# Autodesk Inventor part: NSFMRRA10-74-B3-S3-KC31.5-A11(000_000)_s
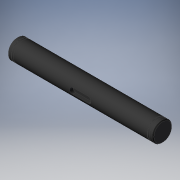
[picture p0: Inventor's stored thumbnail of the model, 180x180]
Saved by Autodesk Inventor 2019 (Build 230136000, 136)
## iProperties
Created: 2022-11
Part Number: NSFMRRA10-74-B3-S3-KC31.5-A11(000_000)_s
Material: Generic
Catalog Web Link: www.cadenas.de
Description: NSFMRR, SFMRR, PSFMRR, SSFMRR, NSFHRR, SFHRR, PSFHRR, SSFHRR, NSFRR, SFRR, PSFRR, SSFRR, NSFMRRA, SFMRRA, PSFMRRA, SSFMRRA, NSFHRRA, SFHRRA, PSFHRRA, SSFHRRA, N
Vendor: MISUMI
Document SubType Name: Modeling
Designer: psAdmin
Manufacturer: MISUMI
Mass: 5.73651 g
Surface Area: 25.2511 cm^2
Volume: 5.73651 cm^3
Density: 1 g/cm^3
Appearance: PSOLRGB-175-175-175
Category: PARTsolutions
Company: MISUMI
Title: NSFMRRA10-74-B3-S3-KC31.5-A11
Author: Cadenas PARTsolutions
Comments: Rotary Shafts - Retaining Ring Grooves on Both Ends - Standard
PSOL_IDENT_0: {$CADENAS_DATA/23d-libs/misumi/metric/11_rotary_shafts/11_components/psfrra/psfrra.prj},808 {VTYP=3D
PSOL_IDENT_1: },{NB=NSFMRRA10-74-B3-S3-KC31.5-A11(000_000)_s},{LINA=NSFMRRA10-74-B3-S3-KC31.5-A11},{NN=NSFMRR, SFM
PSOL_IDENT_2: RR, PSFMRR, SSFMRR, NSFHRR, SFHRR, PSFHRR, SSFHRR, NSFRR, SFRR, PSFRR, SSFRR, NSFMRRA, SFMRRA, PSFMR
PSOL_IDENT_3: RA, SSFMRRA, NSFHRRA, SFHRRA, PSFHRRA, SSFHRRA, NSFRRA, SFRRA, PSFRRA, SSFRRA, HFRRA, PHFRRA, PSFRR
PSOL_IDENT_4: PSFRRA, PSFHRR, PSFHRRA, SSFRR, SSFRRA, SSFHRR, SSFHRRA, PPSFRR, PPSFRRA, PPSFHRR, PPSFHRRA, SSSFRR,
PSOL_IDENT_5: SSSFRRA, SSSFHRR, SSSFHRRA_shaft},{DATE=21.04.2022 07:40:13},{GEOMDATE=27.07.2021 07:13:06},{VERSIO
PSOL_IDENT_6: N=},{LINEID=30},{WBVAR=TS,TYS,MAT,ST,ALT1,L,B,S,ALT2,KC,A,WKC,C,K,E,KZ,Z,ALT3,FC,GALT3,WFC,J,WALT3,V
PSOL_IDENT_7: ,ALT4,SFC,SG,AG,ALT5,UC,ALT7,SC,ALT10,KWC,ALT11,WC,ALT32,CD,ALT34,TCJ,WTCJ,XT,HCJ,WHCJ,XH},{WBNUMERI
PSOL_IDENT_8: C=L,B,S,KC,A,WKC,C,K,E,KZ,Z,FC,GALT3,WFC,J,WALT3,V,SFC,SG,AG,UC,SC,KWC,WC,TCJ,WTCJ,XT,HCJ,WHCJ,XH}
PSOL_IDENT_9: {NB=NSFMRRA10-74-B3-S3-KC31.5-A11(000_000)_s},{LINA=NSFMRRA10-74-B3-S3-KC31.5-A11},{KT=DUMMY},{PN=NS
PSOL_IDENT_10: FMRRA10-74-B3-S3-KC31.5-A11},{TYPE=NSFMRRA},{TS=SWR},{TYS=H9},{TYSALG= 'H9','h9 (Cold-drawn)','H7','
PSOL_IDENT_11: h7 (Ground)','G6','g6 (Ground)' },{MAT=S45C},{MATALG= 'S45C','S45C Equivalent', 'SUS304','SUS304' },
PSOL_IDENT_12: {ST=},{STALG= '','' },{D=10.0},{ALT1=},{ALT1ALG= '','w/o LKC (Changes L Tolerance)','-LKC','with LKC
PSOL_IDENT_13: (Changes L Tolerance)' },{L=74.0},{LALG=[15:800/0.1]},{LMIN=15},{LMAX=800},{NOTE=25},{B=3.0},{BALG=
PSOL_IDENT_14: [3:70/0.1]},{BMAX=70},{S=3.0},{SALG=[3:69/0.1]},{SMAX=69},{MM=1.15},{DD=9.6},{ARR=STWS10},{ALT2=KC},
PSOL_IDENT_15: {ALT2ALG= '', 'w/o Key Grooves','KC','with KC (Key Groove)','WKC','with WKC (Two Key Grooves)','KCWK
PSOL_IDENT_16: C','with KC + WKC (Three Key Grooves)','KZ','with KC + WKC + KZ (Four Key Grooves)' },{ALT2PN=-KC31.
PSOL_IDENT_17: 5-A11},{KC=31.5},{KCALG=[0:71/0.1]},{KCMIN=0},{KCMAX=71},{A=11.0},{AALG=[3:42.5/0.1]},{AMIN=3},{AMAX=
PSOL_IDENT_18: 42.5},{WKC=0.0},{WKCALG=[0]},{WKCMIN=0},{WKCMAX=0},{C=0.0},{CALG=[0]},{CMIN=3},{CMAX=0},{K=0.0},{KAL
PSOL_IDENT_19: G=[0]},{KMIN=0},{KMAX=69},{E=0.0},{EALG=[0]},{EMIN=3},{EMAX=72},{KZ=0.0},{KZALG=[0]},{KZMIN=76},{KZM
PSOL_IDENT_20: AX=71},{Z=0.0},{ZALG=[0]},{ZMIN=3},{ZMAX=74},{CIFKC=2},{CIFWKC=1},{CIFK=1},{CIFKZ=2},{PCUT3D=0},{QCU
PSOL_IDENT_21: T3D=0},{BB=3},{BBALT2=3},{TT=1.8},{TTALT2=1.8},{ALT3=},{ALT3ALG= '', 'w/o Set Screw Flat','FC','with
PSOL_IDENT_22: FC (Adds a Set Screw Flat)','WFC','with WFC (Adds Two Set Screw Flats)','FCWFC','with FC + WFC (Add
PSOL_IDENT_23: s Three Set Screw Flats)' },{ALT3PN=},{FC=0},{FCALG=[0]},{FCMIN=0},{FCMAX=73},{GALT3=0},{GALT3ALG=[0
PSOL_IDENT_24: ]},{GALT3MIN=1},{GALT3MAX=70},{GALT3MAX2=68},{GALT3MAX3=70},{WFC=0},{WFCALG=[0]},{WFCMIN=0},{WFCMIN2=
PSOL_IDENT_25: 2},{WFCMAX=70},{WFCMAX2=-3},{WFCMAX3=-4},{J=0},{JALG=[0]},{JMIN=1},{JMAX=70},{JMAX2=-2},{JMAX3=-5},{
PSOL_IDENT_26: WALT3=0},{WALT3ALG=[0]},{WALT3MIN=0},{WALT3MIN2=76},{WALT3MAX=71},{WALT3MAX2=71},{V=0},{VALG=[0]},{V
PSOL_IDENT_27: MIN=1},{VMAX=70},{VMAX2=70},{CIFFC=0},{H=0},{ALT4=},{ALT4ALG= '', 'w/o SFC (2 Set Screw Flats (Angle
PSOL_IDENT_28: Specified))', 'SFC'  , 'with SFC (2 Set Screw Flats (Angle Specified))'},{ALT4PN=},{SFC=0},{SFCALG=
PSOL_IDENT_29: [0]},{SFCMIN=0},{SFCMAX=73},{SG=0},{SGALG=[0]},{SGMIN=1},{SGMAX=70},{AG=0},{AGALG=[0]},{CIFSFC=0},{A
PSOL_IDENT_30: LT5=},{ALT5ALG= '', 'w/o UC (Slit Cam Groove)', 'UC', 'with UC (Slit Cam Groove)'},{ALT5PN=},{UC=0},
PSOL_IDENT_31: {UCALG=[0]},{UCMIN=1},{UCMAX=68},{DDALT5=8},{LL1=0},{ALT7=},{ALT7ALG= '', 'w/o SC (Wrench Flats)', '
PSOL_IDENT_32: SC', 'with SC (Wrench Flats)'},{ALT7PN=},{SC=0},{SCALG=[0]},{SCMIN=0},{SCMAX=74},{WALT7=0},{LL2=0},{
PSOL_IDENT_33: CIFSC=0},{ALT10=},{ALT10ALG= '','Not applicable' },{ALT10PN=},{KWC=0},{KWCALG=[0]},{KWCMIN=1},{KWCMA
PSOL_IDENT_34: X=0},{WALT10=8},{ALT11=},{ALT11ALG= '','Not applicable' },{ALT11PN=},{WC=0.0},{WCALG=[0]},{ALT32=},{
PSOL_IDENT_35: ALT32ALG=  '','w/o CD (Changes Part D Chamfering)','-CD', 'with CD (Changes Part D Chamfering)' },{C
PSOL_IDENT_36: D=},{CDALG= '','N/A' },{CD3D=0.5},{CIF32=0},{CIF320=0},{CIF32B=0},{CIF32S=0},{ALT32PN=},{ERRORPN=},{
PSOL_IDENT_37: ERRORRALT2=OK},{ERRORRALT3=OK},{ERRORRALT4=NG},{ERRORRALT5=NG},{ERRORRALT7=NG},{ERRORRALT10=OK},{ERR
PSOL_IDENT_38: ORALT23=OK},{ERRORALT24=OK},{ERRORALT25=OK},{ERRORALT27=OK},{ERRORALT210=OK},{ERRORALT34=OK},{ERRORA
PSOL_IDENT_39: LT35=OK},{ERRORALT37=OK},{ERRORALT310=OK},{ERRORALT45=OK},{ERRORALT47=OK},{ERRORALT410=OK},{ERRORALT
PSOL_IDENT_40: 75=OK},{ERRORALT510=OK},{ERRORALT710=OK},{ALT34=},{ALT34ALG= '','Not applicable'},{TCJ=0},{WTCJ=0},{
PSOL_IDENT_41: XT=0},{TM=4},{TCJALG=[0]},{TCJMIN=7.000},{TCJMAX=34.000},{TCJMAX1=34.000},{HCJ=0},{WHCJ=0},{XH=0},{H
PSOL_IDENT_42: P=4},{HCJALG=[0]},{HCJMIN=7.000},{HCJMAX=34.000},{HCJMAX1=34.000},{LCJ=0},{LMINX=15},{XALG=[0]},{XCJ
PSOL_IDENT_43: MIN=7},{WTCJALG=[0]},{WHCJALG=[0]},{XHALG=[0]}
NB: NSFMRRA10-74-B3-S3-KC31.5-A11(000_000)_s
NN: NSFMRR, SFMRR, PSFMRR, SSFMRR, NSFHRR, SFHRR, PSFHRR, SSFHRR, NSFRR, SFRR, PSFRR, SSFRR, NSFMRRA, SFMRRA, PSFMRRA, SSFMRRA, NSFHRRA, SFHRRA, PSFHRRA, SSFHRRA, N
NT: Rotary Shafts - Retaining Ring Grooves on Both Ends - Standard
NBSYN: $PN.($ALT34.$TCJ.$WTCJ.$XT._$HCJ.$WHCJ.$XH.)_s
LINA: NSFMRRA10-74-B3-S3-KC31.5-A11
CATALOG: Misumi
PN: NSFMRRA10-74-B3-S3-KC31.5-A11
TS: With Retaining Ring
TYS: h9 (Cold-drawn)
MAT: S45C Equivalent
D: 10
ALT1: w/o LKC (Changes L Tolerance)
L: 74
B: 3
S: 3
MM: 1.15
DD: 9.6
ALT2: with KC (Key Groove)
KC: 31.5
A: 11
WKC: 0
C: 0
K: 0
E: 0
KZ: 0
Z: 0
ALT3: w/o Set Screw Flat
FC: 0
GALT3: 0
WFC: 0
J: 0
WALT3: 0
V: 0
ALT4: w/o SFC (2 Set Screw Flats (Angle Specified))
SFC: 0
SG: 0
AG: 0
ALT5: w/o UC (Slit Cam Groove)
UC: 0
ALT7: w/o SC (Wrench Flats)
SC: 0
ALT10: Not applicable
KWC: 0
ALT11: Not applicable
WC: 0
ALT32: w/o CD (Changes Part D Chamfering)
CD: N/A
ALT34: Not applicable
TCJ: 0
WTCJ: 0
XT: 0
HCJ: 0
WHCJ: 0
XH: 0
SUPPLIER: MISUMI
ARTICLENO: NSFMRRA10-74-B3-S3-KC31.5-A11(000_000)_s
BOMINFO: NSFMRRA10-74-B3-S3-KC31.5-A11
CREATOR: CADENAS GmbH
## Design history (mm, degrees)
sketch "Sketch_1"
  geometry: L1 (74, 0)-(0, 0); L2 (0, 0)-(0, 4.5); L3 (0, 4.5)-(0.5, 5); L4 (0.5, 5)-(73.5, 5); L5 (73.5, 5)-(74, 4.5); L6 (74, 4.5)-(74, 0); L7 (74, 0)-(0, 0)
  constraints: 14 end point
revolve "Revolution1" sketch "Sketch_1" stored, may be unused: angle "d0" = 360 deg
sketch "_____10"
  geometry: L1 (33, -1.5)-(41, -1.5); L2 (41, 1.5)-(33, 1.5); A1 r 1.5 centre (33, 0) between (33, 1.5) and (33, -1.5); A2 r 1.5 centre (41, 0) between (41, -1.5) and (41, 1.5)
  constraints: 4 end point, 4 point on circle, 2 centre point
extrude "Extrusion1" cut sketch "_____10" distance "d1" = 1.8; taper "d2" = 0 deg
sketch "_____5"
  geometry: C1 r 10 at (0, 0); C2 r 4.8 at (0, 0); 2 further points
  constraints: 2 centre point
extrude "Extrusion2" cut sketch "_____5" distance "d3" = 1.15; taper "d4" = 0 deg
sketch "_____6"
  geometry: C1 r 10 at (0, 0); C2 r 4.8 at (0, 0); 2 further points
  constraints: 2 centre point
extrude "Extrusion3" cut sketch "_____6" distance "d5" = 1.15; taper "d6" = 0 deg
node "COMBINATION_MODULE_XY"
node "COMBINATION_MODULE_YZ"
node "COMBINATION_MODULE_ZX"
node "COMBINATION_MODULE_X"
node "COMBINATION_MODULE_Y"
node "COMBINATION_MODULE_Z"
node "COMBINATION_MODULE_Center"
node "to_ring_b_XY"
node "to_ring_b_YZ"
node "to_ring_b_ZX"
node "to_ring_b_X"
node "to_ring_b_Y"
node "to_ring_b_Z"
node "to_ring_b_Center"
node "to_ring_s_XY"
node "to_ring_s_YZ"
node "to_ring_s_ZX"
node "to_ring_s_X"
node "to_ring_s_Y"
node "to_ring_s_Z"
node "to_ring_s_Center"
body "Solid1"
other parameters: "d7" = 0
